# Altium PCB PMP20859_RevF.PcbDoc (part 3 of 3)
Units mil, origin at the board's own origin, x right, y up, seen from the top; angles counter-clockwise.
Board outline 5000 x 4200 mil, 4 copper layers (Top Layer, Signal Layer 1, Signal Layer 2, Bottom Layer), stack 61.2 mil thick; 264 components, 163 nets, 897 pads, 223 vias.
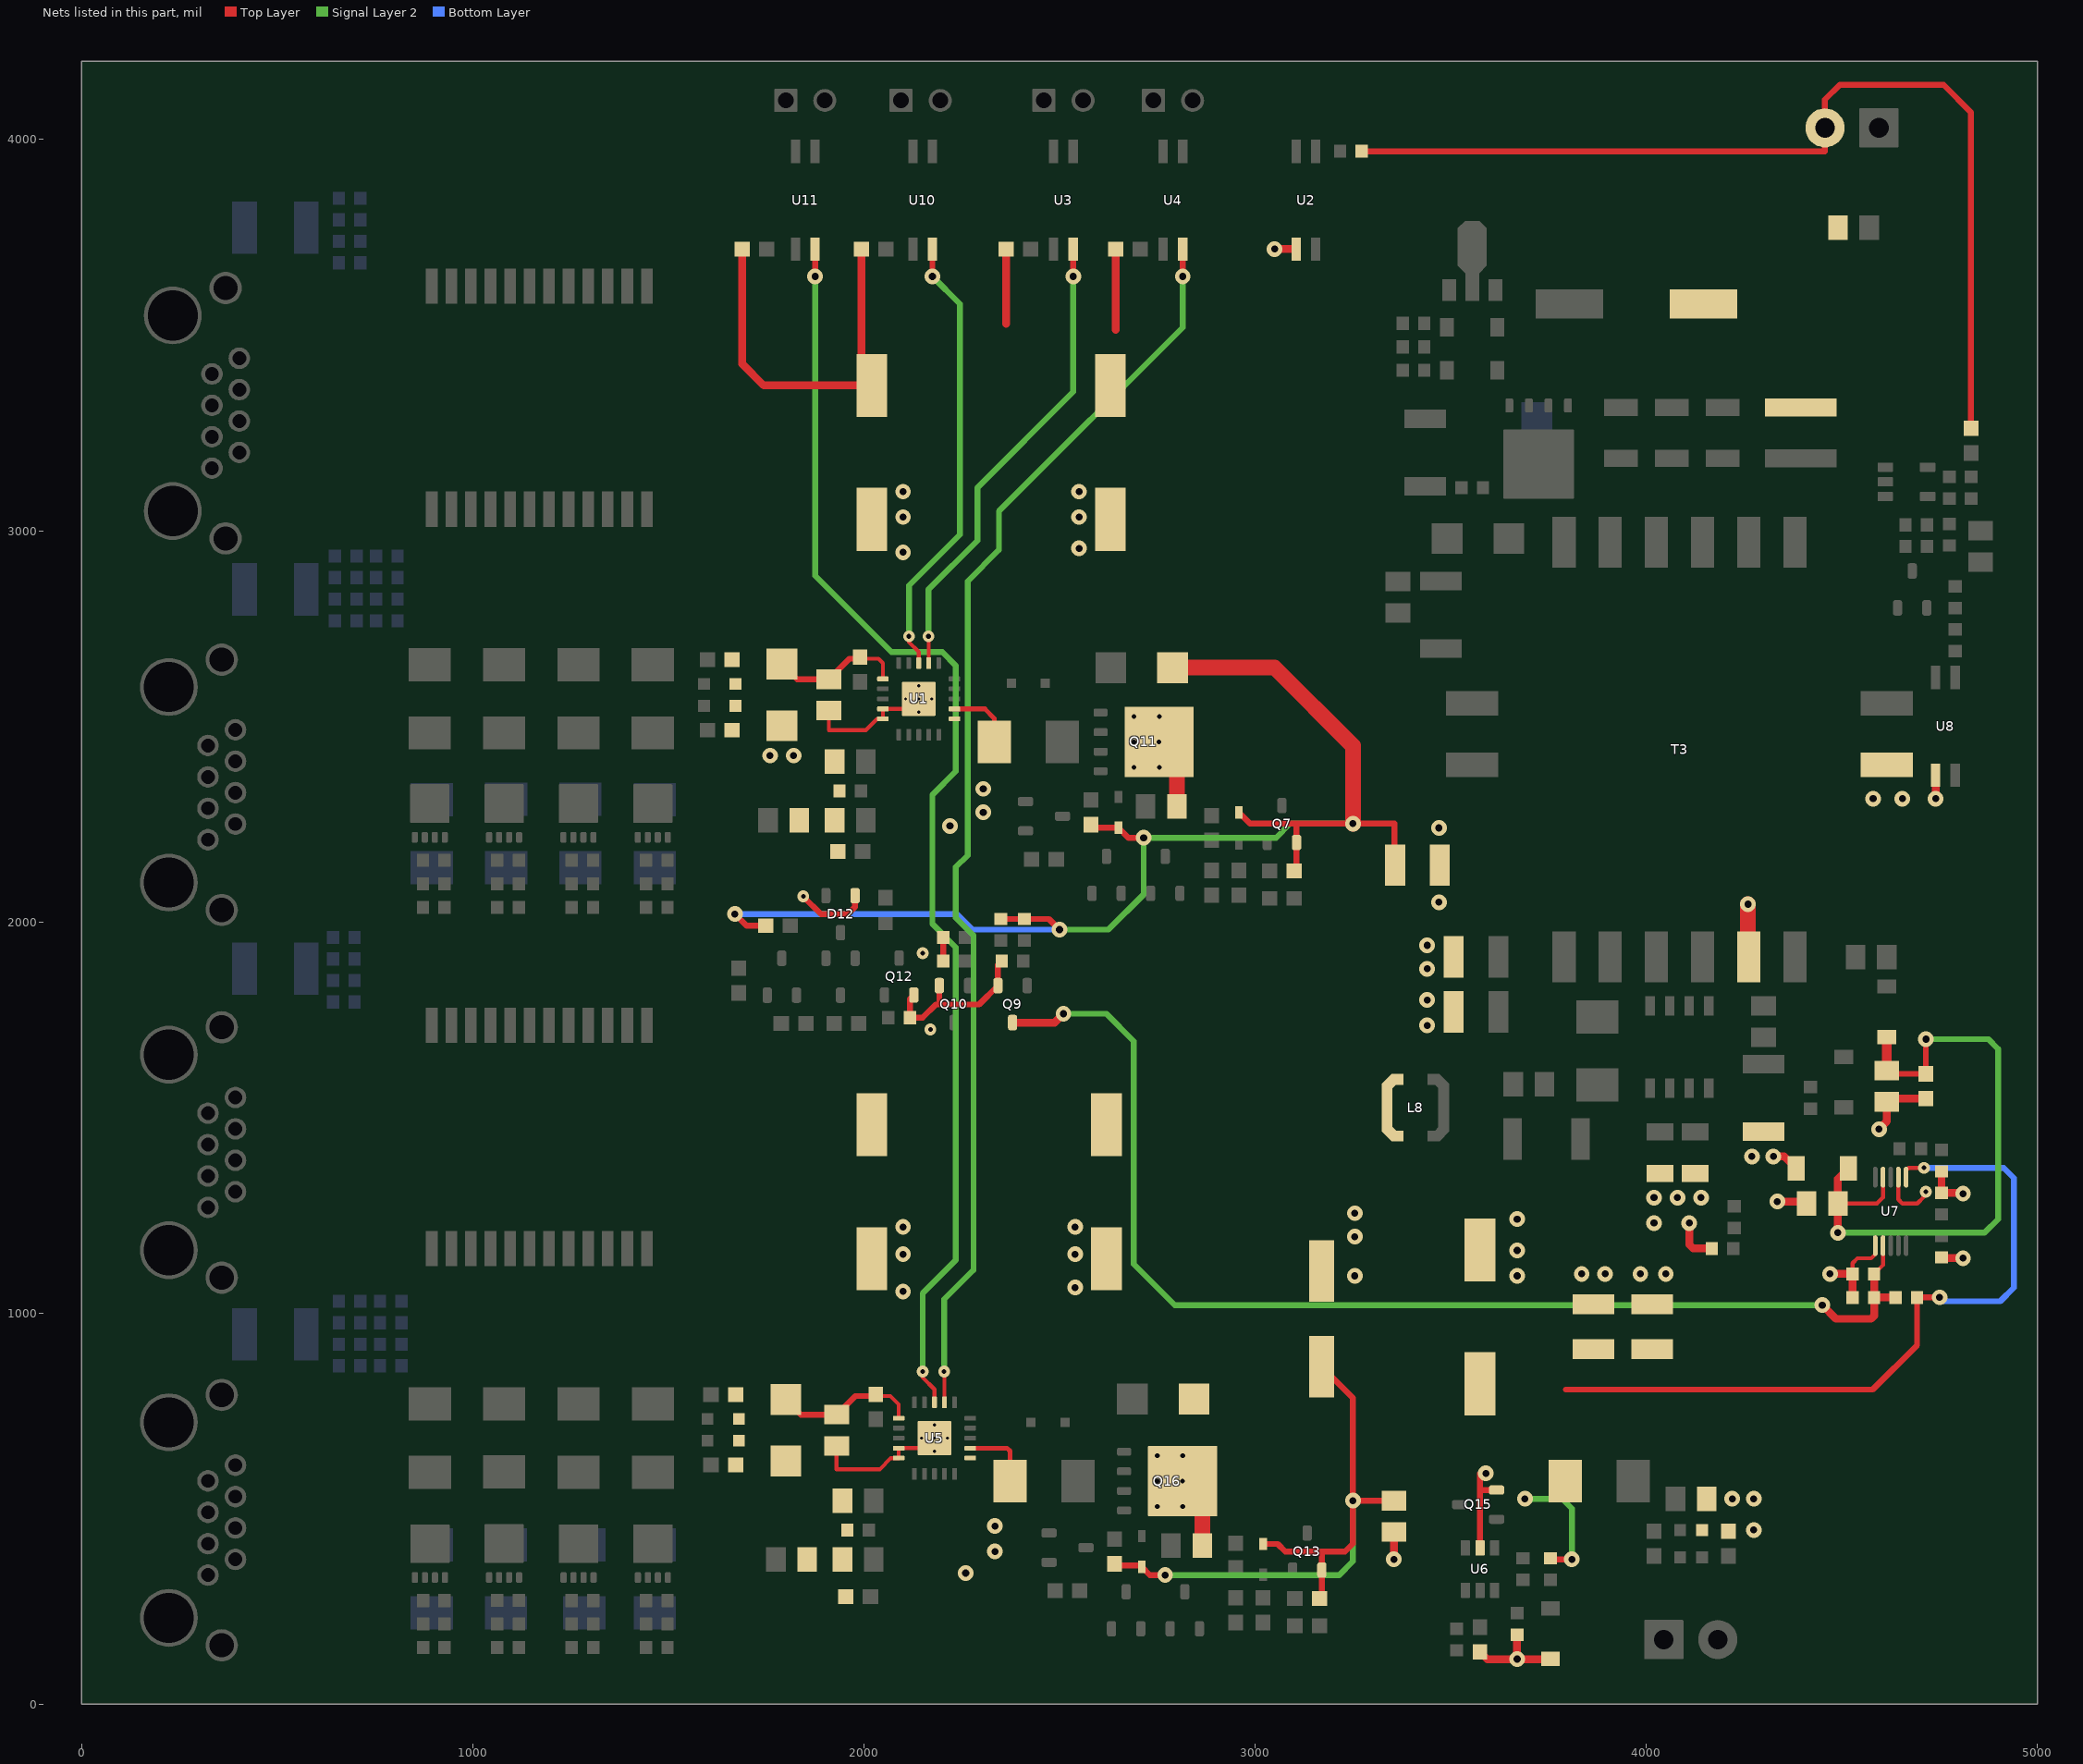
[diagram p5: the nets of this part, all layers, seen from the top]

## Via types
v1: diameter 40, hole 18, Top Layer to Bottom Layer, 185 vias
v2: diameter 30, hole 12, Top Layer to Bottom Layer, 28 vias
v3: diameter 19.68, hole 7.87, Top Layer to Bottom Layer, 10 vias

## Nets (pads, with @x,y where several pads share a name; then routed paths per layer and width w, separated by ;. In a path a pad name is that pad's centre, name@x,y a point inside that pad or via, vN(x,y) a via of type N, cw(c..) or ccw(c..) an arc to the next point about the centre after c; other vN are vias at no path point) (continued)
PWRGND: C30.2 C31.2 C32.2 C33.2 C40.1 C47.2 C48.2 C49.2 C51.2 C53.1 C54.2 C57.1 C58.2 C59.2 C60.1 C61.1 C64.2 C68.1 C69.1 C70.2 C100.1 C101.1 D12.1 D24.2 L6.2 Q9.2 Q10.2 Q11.5 Q11.6 Q11.7 Q11.8 Q11.9@2754.57,2460 Q12.2 Q15.2 Q16.5 Q16.6 Q16.7 Q16.8 Q16.9@2814.57,570 R53.1 R55.1 R57.1 R77.1 R86.1 R87.1 R89.1 R90.1 R93.1 R94.1 T3.5 U2.3 U6.2 U7.2 U7.6 U8.3 | length 2809.7
  Top Layer w10: R86.1@4527.44,1099.69 4527.44,1127.44 4540,1140 4575,1140 4585.63,1150.63 U7.6@4585.63,1178.98 ; U7.2@4644.69,1340.39 4644.69,1290.31 4655,1280 4692.83,1280 v2@4710,1297.17
  Top Layer w15: v2(1845,2065) 1890,2020 1959.37,2020 1977.4,2038.03 D12.1@1977.4,2066.93 ; Q12.2@2127.4,1812.76 2117.56,1802.91 R57.1@2117.56,1755 2150,1755 2183.7,1788.7 2294.37,1788.7 Q9.2@2342.6,1836.93 2342.6,1889.84 R53.1@2352.44,1899.68 ; 2192.6,1797.6 Q10.2@2192.6,1836.93 ; R55.1@2202.13,1900 R55.1@2202.44,1899.68 C30.2@2202.44,1959.68 ; U6.2@3575,399.13 v1@3575,590 ; 3577.6,547.4 Q15.2@3617.24,547.4
  Top Layer w20: v1(3050,3720) U2.3@3105,3720 ; v1(3355,370) C51.2@3355,440 ; R77.1@3575,133.5 3593.5,115 v1(3670,115) ; C40.1@3670,177.44 v1(3670,115) ; D24.2@3754.47,115 v1(3670,115) ; v1(4110,1230) 4110,1175 4120,1165 C64.2@4167.44,1165 ; v1(4325,1400) 4353.07,1400 C54.2@4383.07,1370 ; v1(4335,1285) C53.1@4405,1285 ; v1@4470.31,1099.69 R86.1@4527.44,1099.69 C60.1@4527.44,1039.69 ; v1(4595,1470) 4615,1490 C59.2@4615,1540 4623.5,1548.5 C58.2@4715,1548.5 ; v1(4740,2315) U8.3@4740,2375 ; R89.1@4755,1362.13 R87.1@4755,1307.24 v1@4807.76,1307.24 ; C61.1@4757.13,1140 v1(4810,1140)
  Top Layer w40: v2(2754.57,2460) 2800,2414.57 C68.1@2800,2295 ; v2(2814.57,570) 2865,519.57 C69.1@2865,405 ; T3.5@4260,1912.15 v1(4260,2045)
  other v1: 4275,445 4220,525 4275,525 3590,590 3255,1095 3670,1095 3835,1100 3895,1100 3985,1100 4050,1100 4470,1100 3670,1160 3255,1195 4020,1230 3670,1240 3255,1255 4020,1295 4080,1295 4140,1295 4810,1305 4270,1400 3440,1735 3440,1800 3440,1880 3440,1940 3470,2050 3470,2240 4580,2315 4655,2315
  other v2: 2750,505 2815,505 2750,570 2750,635 2815,635 4715,1310 2170,1725 2150,1920 2690,2395 2755,2395 2690,2460 2690,2525 2755,2525
RTN1: C25.2 C26.2 D16.1 U1.11 U1.12 | length 171.9
  Top Layer w12: U1.12@2231.54,2544.41 2309.09,2544.41 2332.99,2520.51 D16.1@2332.99,2460
  other v1: 2220,2245 2305,2280 2305,2340 2100,2945 2550,2955 2100,3035 2550,3035 2100,3100 2550,3100
RTN2: C35.2 C36.2 D26.1 U5.11 U5.12 | length 181.3
  Top Layer w12: U5.12@2271.85,654.41 2365.59,654.41 2373.31,646.69 D26.1@2373.31,570
  other v1: 2260,335 2335,390 2335,455 2100,1055 2540,1065 2100,1150 2540,1150 2100,1220 2540,1220
SS: C60.2 Q9.3 R82.1 R86.2 U7.7 | length 3122.7
  Top Layer w10: R86.2@4582.56,1099.69 4605.31,1122.44 U7.7@4605.31,1178.98
  Top Layer w20: Q9.3@2380,1742.44 2487.44,1742.44 v1(2510,1765) ; v1(4450,1020) 4485,985 4575,985 4582.56,992.56 C60.2@4582.56,1039.69 ; R86.2@4582.56,1099.69 C60.2@4582.56,1039.69 ; R82.1@4637.44,1039.69 C60.2@4582.56,1039.69
  Signal Layer 2 w15: v1(2510,1765) 2620,1765 2690,1695 2690,1125 2795,1020 v1(4450,1020)
TPH1: U1.18 U10.2 | length 1151.7
  Top Layer w10: v2(2115,2730) 2115,2715 2140,2690 U1.18@2140,2661.54
  Top Layer w15: v1(2175,3650) U10.2@2175,3720
  Signal Layer 2 w15: v2(2115,2730) 2115,2860 2245,2990 2245,3580 v1(2175,3650)
TPH2: U5.18 U11.2 | length 3271.2
  Top Layer w10: v2(2150,850) 2150,835 2180.32,804.68 U5.18@2180.32,771.54
  Top Layer w15: v1(1875,3650) U11.2@1875,3720
  Signal Layer 2 w15: v1(1875,3650) 1875,2885 2070,2690 2200,2690 2235,2655 2235,2385 2175,2325 2175,1995 2235,1935 2235,1135 2150,1050 v2(2150,850)
TPL1: U1.17 U3.2 | length 1211.1
  Top Layer w10: U1.17@2165.59,2661.54 v2@2165.59,2729.41
  Top Layer w15: v1(2535,3650) U3.2@2535,3720
  Signal Layer 2 w15: v2(2165,2730) 2165,2850 2290,2975 2290,3110 2535,3355 v1(2535,3650)
TPL2: U4.2 U5.17 | length 3237.5
  Top Layer w10: U5.17@2205.91,771.54 v2@2205.91,849.09
  Top Layer w15: v1(2815,3650) U4.2@2815,3720
  Signal Layer 2 w15: v2(2205,850) 2205,1035 2280,1110 2280,1965 2235,2010 2235,2140 2265,2170 2265,2871.02 2345,2951.02 2345,3049.69 2815,3519.69 v1(2815,3650)
VCC: C53.2 C54.1 C58.1 C59.1 D30.1 U7.4 | length 1675.3
  Top Layer w10: C53.2@4490,1280 4590,1280 4605.31,1295.32 U7.4@4605.31,1340.39
  Top Layer w15: C59.1@4615,1620 4623.5,1611.5 C58.1@4715,1611.5 v1(4715,1700)
  Top Layer w20: v1(4490,1205) C53.2@4490,1280 4490,1343.07 C54.1@4516.93,1370
  Top Layer w25: C59.1@4615,1620 D30.1@4615,1705.53
  Signal Layer 2 w15: v1(4490,1205) 4600,1205 4865,1205 4900,1240 4900,1675 4875,1700 v1(4715,1700)
VDD: C2.1 C14.1 C25.1 C26.1 C27.2 C31.1 C35.1 C36.1 C37.2 C47.1 C51.1 C70.1 C100.2 C101.2 D9.1 D10.1 D11.1 D13.1 D18.1 D19.1 D20.1 D21.1 D34.1 L1.2 L3.2 L8.1 Q7.2 Q13.2 R33.2 R34.2 R35.2 R36.1 R37.2 R38.1 R49.2 R52.1 R58.1 R59.1 R60.2 R61.2 R62.2 R69.2 R82.2 U1.1 U5.1 U7.1 | length 9662
  Top Layer w10: R35.2@1990,2672.56 2037.44,2672.56 2048.46,2661.54 U1.1@2048.46,2621.18 ; R62.2@2030.32,787.56 2067.44,787.56 2088.78,766.22 U5.1@2088.78,731.18 ; U7.1@4664.37,1364.37 4670.98,1370.98 v2(4710,1370.98)
  Top Layer w15: v1(1670,2020) 1700,1990 R33.2@1748.5,1990 ; D11.1@1790.32,2658.74 1829.05,2620 C27.2@1910.32,2620 1962.87,2672.56 R35.2@1990,2672.56 ; D21.1@1800.32,778.74 1839.05,740 C37.2@1930.32,740 1977.87,787.56 R62.2@2030.32,787.56 ; R52.1@2350,2007.24 2472.76,2007.24 v1(2500,1980) ; R37.2@2580.32,2248.5 2588.19,2240.63 D9.1@2650.32,2240.63 2675.94,2215 v1(2715,2215) ; R61.2@2640.32,358.5 2640.32,354.68 2706.26,354.68 D20.1@2710.32,350.63 2730.94,330 v1(2770,330) ; D10.1@2958.64,2279.37 2987.02,2250.99 v1(3250,2250.99) 3355.99,2250.99 C47.1@3355.99,2146.92 ; D19.1@3020.32,409.37 3057.77,409.37 3077.14,390 3230,390 3250,410 v1(3250,520) ; R34.2@3100.14,2130 3106.04,2135.91 Q7.2@3106.04,2202.76 3106.04,2249.95 ; R60.2@3164.74,270 3170.65,275.91 Q13.2@3170.65,342.76 3170.65,389.35 ; C31.1@3170,862.95 3250,782.95 v1(3250,520) ; C51.1@3355,520 v1(3250,520) ; R69.2@3755,372.56 3757.56,370 v1(3810,370) v1@3807.44,372.56 ; 3795,804.06 4579.06,804.06 4692.56,917.56 R82.2@4692.56,1039.69 4749.69,1039.69 v1(4750,1040)
  Top Layer w20: R38.1@1688.5,3720 1688.5,3426.5 1743.74,3371.26 C25.1@2020,3371.26 1993.5,3397.76 R36.1@1993.5,3720 ; 2363.5,3528.5 R58.1@2363.5,3720 ; 2643.5,3513.5 R59.1@2643.5,3720
  Top Layer w40: D13.1@2788.74,2650 3050,2650 3250,2450 v1(3250,2250.99)
  Signal Layer 2 w15: v1(2500,1980) 2625,1980 2715,2070 v1(2715,2215) 3053.33,2215 3089.32,2250.99 v1(3250,2250.99) ; v1(2770,330) 3215,330 3250,365 v1(3250,520) ; v1(3690,525) 3785,525 3810,500 v1(3810,370)
  Bottom Layer w15: v1(1670,2020) 2237.6,2020 2277.6,1980 v1(2500,1980) ; v2(4710,1370.98) 4914.02,1370.98 4940,1345 4940,1065 4905,1030 4760,1030 v1(4750,1040)
VOUT: C46.1 C50.1 J8.2 L7.2 R56.2 R92.1 | length 2546.7
  Top Layer w15: R56.2@3272.56,3970 4457,3970 J8.2@4457,4030 4457,4102 4495,4140 4760,4140 4830.31,4069.69 R92.1@4830.31,3257.56
VSS_1: C2.2 C27.1 D11.2 L2.2 R42.2 R47.1 R48.1 R50.2 R54.1 U1.4 U1.5 U1.21@2140,2570 | length 328.3
  Top Layer w10: C27.1@1910.32,2540 1910,2539.69 1910,2490 2005,2490 2033.82,2518.82 U1.5@2048.46,2518.82 U1.4@2048.46,2544.41 2114.41,2544.41 v3(2140,2570)
  other v1: 1760,2425 1820,2425
  other v3: 2140,2536.54 2106.54,2570 2173.46,2570 2140,2603.46
VSS_2: C14.2 C37.1 D21.2 L4.2 R67.2 R70.2 R71.1 R72.1 R75.1 U5.4 U5.5 U5.21@2180.32,680 | length 358.6
  Top Layer w10: C37.1@1930.32,660 1930,659.69 1930,600 2040,600 2068.82,628.82 U5.5@2088.78,628.82 U5.4@2088.78,654.41 2154.72,654.41 v3(2180.32,680)
  other v3: 2180.32,646.54 2146.85,680 2213.78,680 2180.32,713.46
pads on no net: D12.2 D15.2 D17.2 D23.2 D25.2 Q1.9@1421.61,2323.37 Q1.9@1433.92,2268.94 Q1.9@1433.92,2304.57 Q1.9@1447.2,2323.37 Q1.9@1460,2290 Q1.9@1472.8,2323.37 Q1.9@1486.08,2268.94 Q1.9@1486.08,2304.57 Q1.9@1498.39,2323.37 Q2.9@1041.61,2323.37 Q2.9@1053.92,2268.94 Q2.9@1053.92,2304.57 Q2.9@1067.2,2323.37 Q2.9@1080,2290 Q2.9@1092.8,2323.37 Q2.9@1106.08,2268.94 Q2.9@1106.08,2304.57 Q2.9@1118.39,2323.37 Q3.9@1231.61,2323.37 Q3.9@1243.92,2268.94 Q3.9@1243.92,2304.57 Q3.9@1257.2,2323.37 Q3.9@1270,2290 Q3.9@1282.8,2323.37 Q3.9@1296.08,2268.94 Q3.9@1296.08,2304.57 Q3.9@1308.39,2323.37 Q4.9@851.61,2323.37 Q4.9@863.92,2268.94 Q4.9@863.92,2304.57 Q4.9@877.2,2323.37 Q4.9@890,2290 Q4.9@902.8,2323.37 Q4.9@916.08,2268.94 Q4.9@916.08,2304.57 Q4.9@928.39,2323.37 Q11.9@2700.04,2402.91 Q11.9@2700.04,2460 Q11.9@2700.04,2517.09 Q11.9@2736.65,2460 Q11.9@2770.12,2402.91 Q11.9@2770.12,2460 Q11.9@2770.12,2517.09 Q16.9@2760.04,512.91 Q16.9@2760.04,570 Q16.9@2760.04,627.09 Q16.9@2796.65,570 Q16.9@2830.12,512.91 Q16.9@2830.12,570 Q16.9@2830.12,627.09 Q17.9@3667.91,3154.88 Q17.9@3667.91,3224.96 Q17.9@3725,3154.88 Q17.9@3725,3188.35 Q17.9@3725,3224.96 Q17.9@3782.09,3154.88 Q17.9@3782.09,3224.96 Q20.9@1421.93,430.94 Q20.9@1434.24,376.51 Q20.9@1434.24,412.14 Q20.9@1447.52,430.94 Q20.9@1460.32,397.58 Q20.9@1473.11,430.94 Q20.9@1486.4,376.51 Q20.9@1486.4,412.14 Q20.9@1498.71,430.94 Q21.9@1041.62,431.26 Q21.9@1053.92,376.83 Q21.9@1053.92,412.46 Q21.9@1067.21,431.26 Q21.9@1080,397.89 Q21.9@1092.8,431.26 Q21.9@1106.09,376.83 Q21.9@1106.09,412.46 Q21.9@1118.39,431.26 Q22.9@1231.93,430.94 Q22.9@1244.24,376.51 Q22.9@1244.24,412.14 Q22.9@1257.52,430.94 Q22.9@1270.32,397.58 Q22.9@1283.11,430.94 Q22.9@1296.4,376.51 Q22.9@1296.4,412.14 Q22.9@1308.71,430.94 Q23.9@851.93,430.94 Q23.9@864.24,376.51 Q23.9@864.24,412.14 Q23.9@877.52,430.94 Q23.9@890.32,397.58 Q23.9@903.11,430.94 Q23.9@916.4,376.51 Q23.9@916.4,412.14 Q23.9@928.71,430.94 U1.10 U1.14 U1.15 U1.16 U1.19 U1.20 U1.21@2116.77,2546.77 U1.21@2116.77,2593.23 U1.21@2163.23,2546.77 U1.21@2163.23,2593.23 U5.10 U5.14 U5.15 U5.16 U5.19 U5.20 U5.21@2157.09,656.77 U5.21@2157.09,703.23 U5.21@2203.54,656.77 U5.21@2203.54,703.23 U6.3 U6.4 U9.1 U9.2

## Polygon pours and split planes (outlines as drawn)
PR12_1 on Bottom Layer "BOTTOM_LAYER_PR12_1_P079" (solid, remove dead copper, pour order 79): 1530,2255 1530,2425 1390,2425 1390,2255
PR36_1 on Bottom Layer "BOTTOM_LAYER_PR36_1_P075" (solid, remove dead copper, pour order 75): 1340,2255 1340,2425 1200,2425 1200,2255
PR45_1 on Bottom Layer "BOTTOM_LAYER_PR45_1_P073" (solid, remove dead copper, pour order 73): 1150,2255 1150,2425 1010,2425 1010,2255
PR78_1 on Bottom Layer "BOTTOM_LAYER_PR78_1_P071" (solid, remove dead copper, pour order 71): 960,2255 960,2425 820,2425 820,2255
NetC1_2 on Bottom Layer "BOTTOM_LAYER_NETC1_2_P069" (solid, remove dead copper, pour order 69): 785,2080 1610,2080 1610,2190 785,2190
PR12_2 on Bottom Layer "BOTTOM_LAYER_PR12_2_P067" (solid, remove dead copper, pour order 67): 1530,360 1530,535 1390,535 1390,360
PR36_2 on Bottom Layer "BOTTOM_LAYER_PR36_2_P065" (solid, remove dead copper, pour order 65): 1340,360 1340,535 1200,535 1200,360
PR45_2 on Bottom Layer "BOTTOM_LAYER_PR45_2_P063" (solid, remove dead copper, pour order 63): 1010,360 1010,535 1150,535 1150,360
PR78_2 on Bottom Layer "BOTTOM_LAYER_PR78_2_P061" (solid, remove dead copper, pour order 61): 960,360 820,360 820,535 960,535
NetC13_2 on Bottom Layer "BOTTOM_LAYER_NETC13_2_P059" (solid, remove dead copper, pour order 59): 785,190 1620,190 1620,295 785,295
RTN2 on Bottom Layer "BOTTOM_LAYER_RTN2_P047" (solid, remove dead copper, pour order 47): 2900,1000 2495,1000 2495,250 2300,250 2300,890 1650,890 1650,1620 2900,1620
RTN1 on Bottom Layer "BOTTOM_LAYER_RTN1_P043" (solid, remove dead copper, pour order 43): 2850,2880 2850,3550 1640,3550 1640,2780 2250,2780 2250,2200 2450,2200 2450,2880
GND on Bottom Layer "BOTTOM_LAYER_GND_P050" (solid, remove dead copper, pour order 50): 3040,4150 1700,4150 1699.79,4150 1700.08,3849.7 3325,3849.7 3325,2675 3475,2525 4950,2525 4950,4150
PWRGND on Bottom Layer "BOTTOM_LAYER_PWRGND_P056" (solid, remove dead copper, pour order 56): 2725,50 2725,950 2950,950 2950,1700 1640.39,1700 1640,1700.39 1640,2100 2665,2100 2665,2800 2950,2800 2950,3750 3225,3750 3225,2595 3385,2435 4950,2435 4950,50 4300,50 4300,420 3950,420 3950,50
BSVG on Bottom Layer "BOTTOM_LAYER_BSVG_P057" (solid, pour order 57): 450,3940 60,3940 60,60 450,60
VSS_1 on Bottom Layer "BOTTOM_LAYER_VSS_1_P032" (solid, pour order 32): 2185,2615 2095,2615 2095,2570 1640,2570 1640,2150 2140,2150 2140,2400 2185,2400
VSS_2 on Bottom Layer "BOTTOM_LAYER_VSS_2_P036" (solid, pour order 36): 2225,725 2135,725 2135,690 1650,690 1650,240 2190,240 2190,500 2225,500
RTN2 on Top Layer "TOP_LAYER_RTN2_P048" (solid, remove dead copper, pour order 48): 2300,890 2300,1000 2900,1000 2900,1300 1910,1300 1910,890
RTN1 on Top Layer "TOP_LAYER_RTN1_P039" (solid, pour order 39): 1900,2780 1900,3200 2850,3200 2850,2880 2250,2880 2250,2780
GND on Top Layer "TOP_LAYER_GND_P052" (solid, remove dead copper, pour order 52): 1700,4150 1700,3850 3324.41,3850 3325,3849.41 3325,2675 3475,2525 4950,2525 4950,4150
PWRGND on Top Layer "TOP_LAYER_PWRGND_P054" (solid, remove dead copper, pour order 54): 2725,950 2950,950 2950,1700 2949.61,1700.39 1640,1700.39 1640,2100 2665,2100 2665,2800 2950,2800 2950,3750 3225,3750 3225,2595 3385,2435 4950,2435 4950,50 4300,50 4300,420 3950,420 3950,50 2725,50
AUX on Top Layer "TOP_LAYER_AUX_P030" (solid, pour order 30): 4105,420 3910,420 3910,665 4105,665
RTN1 on Top Layer "TOP_LAYER_RTN1_P040" (solid, pour order 40): 2215,2550 2385,2550 2385,2380 2365,2380 2365,2200 2190,2200 2190,2325 2250,2325 2250,2475 2215,2510
RTN2 on Top Layer "TOP_LAYER_RTN2_P044" (solid, pour order 44): 2255,660 2425,660 2425,250 2230,250 2230,425 2300,425 2300,575 2255,620
NetC38_2 on Top Layer "TOP_LAYER_NETC38_2_P029" (solid, pour order 29): 2495,495 2595,495 2595,535 2685,535 2685,705 2735,705 2735,840 2610,840 2610,650 2495,650
NetC28_2 on Top Layer "TOP_LAYER_NETC28_2_P028" (solid, pour order 28): 2455,2380 2555,2380 2555,2425 2625,2425 2625,2590 2675,2590 2675,2710 2545,2710 2545,2545 2455,2545
VOUT on Top Layer "TOP_LAYER_VOUT_P027" (solid, pour order 27): 4515,3280 4515,4150 4025,4150 4025,3490 4285,3490 4285,3280
NetC42_2 on Top Layer "TOP_LAYER_NETC42_2_P026" (solid, pour order 26): 3535,2845 3330,2845 3330,3040 3535,3040
NetC56_2 on Top Layer "TOP_LAYER_NETC56_2_P025" (solid, pour order 25): 4305,3040 4215,3040 4215,2780 3825,2780 3825,3260 3565,3260 3565,2680 4305,2680
NetC43_1 on Top Layer "TOP_LAYER_NETC43_1_P024" (solid, pour order 24): 3865,2900 3865,3220 4510,3220 4510,2900 4335,2900 4335,3070 3950,3070 3950,2900
NetC52_2 on Top Layer "TOP_LAYER_NETC52_2_P023" (solid, pour order 23): 3950,1630 3950,1380 3715,1380 3715,1630
NetC63_2 on Top Layer "TOP_LAYER_NETC63_2_P022" (solid, pour order 22): 4360,1730 4360,1595 4240,1595 4240,1730
NetQ19_1 on Top Layer "TOP_LAYER_NETQ19_1_P021" (solid, pour order 21): 3980,1600 3980,1430 4360,1430 4360,1500 4125,1500 4125,1600
NetC41_1 on Top Layer "TOP_LAYER_NETC41_1_P020" (solid, pour order 20): 3435,1380 3435,1650 3555,1650 3570,1665 3585,1680 3585,1980 3950,1980 3950,1840 3685,1840 3685,1380
NetC63_1 on Top Layer "TOP_LAYER_NETC63_1_P019" (solid, pour order 19): 4190,1980 4190,1815 4340,1815 4340,1760 4190,1760 4190,1630 3980,1630 3980,1700 3796.5,1700 3796.5,1815 3980,1815 3980,1980
BSVG on Top Layer "TOP_LAYER_BSVG_P058" (solid, pour order 58): 450,3940 450,60 60,60 60,3940
NetC1_1 on Top Layer "TOP_LAYER_NETC1_1_P000" (solid, pour order 0): 820,2590 1620,2590 1620,2710 820,2710
NetC13_1 on Top Layer "TOP_LAYER_NETC13_1_P001" (solid, pour order 1): 820,715 1630,715 1630,820 820,820
PR78_1 on Top Layer "TOP_LAYER_PR78_1_P002" (solid, pour order 2): 820,2550 820,2305 960,2305 960,2550
PR45_1 on Top Layer "TOP_LAYER_PR45_1_P003" (solid, pour order 3): 1150,2305 1010,2305 1010,2550 1150,2550
PR36_1 on Top Layer "TOP_LAYER_PR36_1_P004" (solid, pour order 4): 1340,2305 1340,2550 1200,2550 1200,2305
PR12_1 on Top Layer "TOP_LAYER_PR12_1_P005" (solid, pour order 5): 1530,2305 1530,2550 1390,2550 1390,2305
NetC1_2 on Top Layer "TOP_LAYER_NETC1_2_P006" (solid, pour order 6): 910,2232.11 910,2197.11 890,2197.11 890,2077.11 785,2077.11 785,2232.11
NetC1_2 on Top Layer "TOP_LAYER_NETC1_2_P007" (solid, pour order 7): 1100,2232.11 1100,2197.11 1080,2197.11 1080,2077.11 975,2077.11 975,2232.11
NetC1_2 on Top Layer "TOP_LAYER_NETC1_2_P008" (solid, pour order 8): 1290,2232.11 1290,2197.11 1270,2197.11 1270,2077.11 1165,2077.11 1165,2232.11
NetC1_2 on Top Layer "TOP_LAYER_NETC1_2_P009" (solid, pour order 9): 1480,2232.11 1480,2197.11 1460,2197.11 1460,2077.11 1355,2077.11 1355,2232.11
PR78_2 on Top Layer "TOP_LAYER_PR78_2_P010" (solid, pour order 10): 960,415 960,650 820,650 820,415
PR45_2 on Top Layer "TOP_LAYER_PR45_2_P011" (solid, pour order 11): 1150,415 1010,415 1010,650 1150,650
PR36_2 on Top Layer "TOP_LAYER_PR36_2_P012" (solid, pour order 12): 1340,415 1340,650 1200,650 1200,415
PR12_2 on Top Layer "TOP_LAYER_PR12_2_P013" (solid, pour order 13): 1390,415 1530,415 1530,650 1390,650
NetC13_2 on Top Layer "TOP_LAYER_NETC13_2_P014" (solid, pour order 14): 910,339.68 910,304.68 890,304.68 890,184.68 785,184.68 785,339.68
NetC13_2 on Top Layer "TOP_LAYER_NETC13_2_P015" (solid, pour order 15): 1100,339.68 975,339.68 975,184.68 1080,184.68 1080,304.68 1100,304.68
NetC13_2 on Top Layer "TOP_LAYER_NETC13_2_P016" (solid, pour order 16): 1290,304.68 1290,339.68 1165,339.68 1165,184.68 1270,184.68 1270,304.68
NetC13_2 on Top Layer "TOP_LAYER_NETC13_2_P017" (solid, pour order 17): 1480,339.68 1480,304.68 1460,304.68 1460,184.68 1355,184.68 1355,339.68
VSS_1 on Top Layer "TOP_LAYER_VSS_1_P031" (solid, pour order 31): 1950,2570 1640,2570 1640,2350 1810,2350 1810,2150 1950,2150 1950,2450
VSS_2 on Top Layer "TOP_LAYER_VSS_2_P035" (solid, pour order 35): 1650,690 1970,690 1970,560 1970,240 1830,240 1830,500 1650,500
VDD on Top Layer "TOP_LAYER_VDD_P018" (solid, pour order 18): 3850,640 3850,420 3665,420 3665,640 2950,640 2950,715 2780,715 2780,950 2950,950 2950,1350 1860,1350 1860,715 1650,715 1650,1620 2950,1620 2950,1900 3200,1900 3200,2350 3172.5,2377.5 3150,2400 2950,2400 2950,2610 2725,2610 2725,2835 2950,2835 2950,3250 1845,3250 1845,2595 1640,2595 1640,3550 3225,3550 3225,2595 3347.5,2472.5 3385,2435 3385,1350 3100,1350 3100,950 3250,950 3850,950 4090,950 4090,705 3850,705
RTN2 on Signal Layer 2 "SIGNAL_LAYER_2_RTN2_P046" (solid, remove dead copper, pour order 46): 1650,1620 2900,1620 2900,1000 2495,1000 2495,250 2300,250 2300,890 1650,890
RTN1 on Signal Layer 2 "SIGNAL_LAYER_2_RTN1_P042" (solid, remove dead copper, pour order 42): 1640,3550 2850,3550 2850,2850 2450,2850 2450,2200 2250,2200 2250,2780 1640,2780
GND on Signal Layer 2 "SIGNAL_LAYER_2_GND_P051" (solid, remove dead copper, pour order 51): 4950,2525 3475,2525 3325,2675 3325,3850 1700,3849.5 1700,4149.63 4950,4150
PWRGND on Signal Layer 2 "SIGNAL_LAYER_2_PWRGND_P055" (solid, remove dead copper, pour order 55): 2725,50 2725,950 2950,950 2950,1700 1640,1700 1640,2100 2665,2100 2665,2800 2950,2800 2950,3750 3225,3750 3225,2595 3385,2435 4950,2435 4950,50 4300,50 4300,420 3950,420 3950,50 2725,50
VSS_2 on Signal Layer 2 "SIGNAL_LAYER_2_VSS_2_P038" (solid, pour order 38): 2190,240 1650,240 1650,690 2135,690 2135,725 2225,725 2225,500 2190,500
VSS_1 on Signal Layer 2 "SIGNAL_LAYER_2_VSS_1_P033" (solid, pour order 33): 2140,2150 1640,2150 1640,2570 2095,2570 2095,2615 2185,2615 2185,2400 2140,2400
VSS_2 on Signal Layer 1 "SIGNAL_LAYER_1_VSS_2_P037" (solid, pour order 37): 2190,240 2190,500 2225,500 2225,725 2135,725 2135,690 1895,690 1650,690 1650,240
RTN1 on Signal Layer 1 "SIGNAL_LAYER_1_RTN1_P041" (solid, pour order 41): 2150,2780 1640,2780 1640,3550 2850,3550 2850,2880 2450,2880 2450,2200 2190,2200 2190,2325 2250,2325 2250,2780
RTN2 on Signal Layer 1 "SIGNAL_LAYER_1_RTN2_P045" (solid, pour order 45): 2200,890 1650,890 1650,1620 2900,1620 2900,1000 2495,1000 2495,250 2230,250 2230,425 2300,425 2300,890
GND on Signal Layer 1 "SIGNAL_LAYER_1_GND_P049" (solid, pour order 49): 3475,2525 3325,2675 3325,3850 1700,3850 1700,4150 4950,4150 4950,2525
PWRGND on Signal Layer 1 "SIGNAL_LAYER_1_PWRGND_P053" (solid, pour order 53): 4950,2435 4950,975 4950,50 4300,50 4300,420 4125,420 3950,420 3950,50 2725,50 2725,950 2950,950 2950,1700 1640,1700 1640,2100 2665,2100 2665,2800 2950,2800 2950,3750 3225,3750 3225,2595 3305,2515 3385,2435
VSS_1 on Signal Layer 1 "SIGNAL_LAYER_1_VSS_1_P034" (solid, pour order 34): 2140,2150 2140,2400 2185,2400 2185,2615 2095,2615 2095,2570 1640,2570 1640,2150

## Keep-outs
Keep-Out Layer:
  lines w10: -5,0 ccw(c0,0) 0,-5 ; -5,0 ccw(c0,0) 0,-5 ; -5,0 -5,4200 ; -5,4200 cw(c0,4200) 0,4205 ; -5,4200 cw(c0,4200) 0,4205 ; 0,-5 5000,-5 ; 0,4205 5000,4205 ; 5000,-5 ccw(c5000,0) 5005,0 ; 5000,-5 ccw(c5000,0) 5005,0 ; 5000,4205 cw(c5000,4200) 5005,4200 ; 5000,4205 cw(c5000,4200) 5005,4200 ; 5005,0 5005,4200
  text ".Layer_Name" at 577,-858.49 h60

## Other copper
Top Layer:
  text ".Layer_Name" at 577,-858.49 h60
Bottom Layer:
  text ".Layer_Name" at 577,-858.49 h60

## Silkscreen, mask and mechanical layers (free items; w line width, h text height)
Top Overlay:
  region: 1500,4135 735,4135 735,4035 1500,4035
  lines w8: 1020,235 1030,245 1030,295 ; 1090,105 1090,45 1970,45 ; 1210,225 1220,235 1220,295 ; 1285,45 1285,105 ; 1700,45 1700,215 ; 1840,45 1840,215 ; 2195,215 2195,165 2445,165 ; 2400,165 2400,440 2435,475 ; 2888.64,2320 2913.64,2345 3005,2345 3015,2345 3265,2345 ; 3370,3060 3535,3060 3555,3080 ; 3680,3525 3705,3550 3705,3630 ; 4775,3175 4775,3190 4785,3200 4785,3225 4785,3510
  text "'.PRJ_Number'.PCB_Rev-" at 140,4050 h108.27
  text ".Layer_Name" at 577,-858.49 h60
Bottom Overlay:
  text ".Layer_Name" at 577,-858.49 h60
Top Paste:
  text ".Layer_Name" at 577,-858.49 h60
Bottom Paste:
  text ".Layer_Name" at 577,-858.49 h60
Top Solder:
  text ".Layer_Name" at 577,-858.49 h60
  text ".Layer_Name" at 577,-858.49 h60
Bottom Solder:
  text ".Layer_Name" at 577,-858.49 h60
Drill Guide:
  text ".Layer_Name" at 577,-858.49 h60
M1 Board Outline:
  the board outline again, w10
  text ".Layer_Name" at 577,-858.49 h60
M2 Board Dimensions:
  rectangle: 0,-275 125,-150
  rectangle: 125,-400 500,-275
  lines w7: 0,-275 1000,-275 ; 125,-400 125,-150 ; 250,-400 250,-150 ; 500,-400 500,-150 ; 750,-400 750,-150 ; 0,-400 1000,-400 1000,-150 0,-150 0,-400
  text ".Layer_Name" at 577,-858.49 h60
M3 3D STEP Top:
  text ".Layer_Name" at 577,-858.49 h60
M4 3D STEP Bottom:
  text ".Layer_Name" at 577,-858.49 h60
M5 Assembly Top:
  lines w10: -292,-930.17 6308,-930.17 ; -292,-726.83 6310,-726.83 ; -292,-523.5 -292,-1133.5 3713,-1133.5 6310,-1133.5 6310,-523.5 -291.5,-523.5 -291.5,-1133.5 1284,-1133.5 ; 2173,-1133.5 2173,-523.5 ; 3440,-726.83 3440,-523.5 ; 4280,-726.83 4280,-523.5 ; 4902,-1140 4902,-937.17
  text "COMPONENTS MARKED 'DNP' SHOULD NOT BE POPULATED." at 1153.5,-318.5 h60
  text "ASSEMBLY VARIANT:" at 1153,-434 h60
  text ".VariantName" at 2189,-434 h60
  text "PCB VIEWED FROM TOP SIDE" at -228.5,-655.67 h60
  text "BOARD #:" at 2248,-655.67 h60
  text ".PRJ_Number" at 2793.5,-655.67 h60
  text "REV:" at 3638,-655.67 h60
  text ".PCB_Rev" at 3929.5,-655.67 h60
  text "SVN REV:" at 4476,-655.67 h60
  text ".VersionControl_RevNumber" at 4982,-655.67 h60
  text "TID #:" at 2248,-859 h60
  text ".TID" at 2793.5,-859 h60
  text "PLOT NAME =" at -228.5,-1064.34 h60
  text ".plot_File_Name" at 577,-1064.34 h60
  text "GENERATED    :" at 2250,-1064.34 h60
  text ".Print_Date" at 3119.5,-1064.34 h60
  text ".Print_Time" at 3848.5,-1064.34 h60
  text "TEXAS INSTRUMENTS" at 5113,-1064.34 h60
M6 Assembly Bottom:
  lines w10: -292.5,-727.33 6309.5,-727.33 ; -290.5,-930.67 6309.5,-930.67 ; 1115.5,-1140.5 1115.5,-937.67 ; 1737.5,-727.33 1737.5,-524 ; 2577.5,-727.33 2577.5,-524 ; 3844.5,-1134 3844.5,-524 ; 4733.5,-1134 6309,-1134 6309,-524 -292.5,-524 -292.5,-1134 2304.5,-1134 6309.5,-1134 6309.5,-524
  text "COMPONENTS MARKED 'DNP' SHOULD NOT BE POPULATED." at 6102,-318 h60
  text ".VariantName" at 5058,-434 h60
  text "ASSEMBLY VARIANT:" at 6097,-434 h60
  text ".VersionControl_RevNumber" at 1035.5,-656.17 h60
  text "SVN REV:" at 1541.5,-656.17 h60
  text ".PCB_Rev" at 2088,-656.17 h60
  text "REV:" at 2379.5,-656.17 h60
  text ".PRJ_Number" at 3224,-656.17 h60
  text "BOARD #:" at 3769.5,-656.17 h60
  text "PCB VIEWED FROM BOTTOM SIDE" at 6246,-656.17 h60
  text ".TID" at 3224,-859.5 h60
  text "TID #:" at 3769.5,-859.5 h60
  text "TEXAS INSTRUMENTS" at 904.5,-1064.84 h60
  text ".Print_Time" at 2169,-1064.84 h60
  text ".Print_Date" at 2898,-1064.84 h60
  text "GENERATED    :" at 3767.5,-1064.84 h60
  text ".plot_File_Name" at 5440.5,-1064.84 h60
  text "PLOT NAME =" at 6246,-1064.84 h60
M9 Title Sheet:
  drawing of 57 lines, arcs and shapes, not listed
  text "1" at 739.84,8036.5 h70
  text "2" at 3235.5,8036.5 h70
  text "3" at 5724.84,8036.5 h70
  text "4" at 8231.51,8036.5 h70
  text "5" at 10730.5,8036.5 h70
  text "6" at 13235.5,8036.5 h70
  text "A" at -416.5,6893.5 h70
  text "A" at 14383.5,6893.5 h70
  text "B" at -416.5,4513.5 h70
  text "B" at 14383.5,4513.5 h70
  text "C" at -416.5,2138.5 h70
  text "C" at 14383.5,2138.5 h70
  text "PROJECT TITLE:" at 11343.5,277.5 h45
  text ".PRJ_Title" at 11393.5,144.17 h70
  text "DESIGNED FOR:" at 11343.5,-23.5 h45
  text ".PRJ_Customer" at 11393.5,-163.5 h70
  text "D" at -416.5,-231.5 h70
  text "D" at 14383.5,-231.5 h70
  text "FILE NAME:" at 11343.5,-323.5 h45
  text ".PCB_File_Name_No_Path" at 11393.5,-443.5 h70
  text "Texas Instruments (TI) and/or its licensors do not warrant the accuracy or completeness of this specification" at 6374,-605.34 h45
  text "ENGINEER:" at 11343.5,-613.5 h45
  text "LAYOUT BY:" at 12848.5,-613.5 h45
  text "or any information contained therein. TI and/or its licensors do not warrant that this design will meet" at 6329.01,-718 h45
  text ".PRJ_Engineer" at 11393.5,-768.49 h70
  text ".PCB_Layout" at 12899,-768.49 h70
  text "the specifications, will be suitable for your application or fit for any particular purpose, or will operate in" at 6329.01,-830.67 h45
  text ".Layer_Name" at 577,-858.49 h60
  text "ALTIUM DESIGNER VERSION:" at 12848.5,-923.5 h45
  text "an implementation. TI and/or its licensors do not warrant that the design is production worthy. You should" at 6329.01,-943.33 h45
  text "completely validate and test your design implementation to confirm the system functionality for your application." at 6374,-1056 h45
  text ".print_Scale" at 11393.5,-1056.83 h70
  text ".Application_BuildNumber" at 12899,-1056.83 h70
  text "1" at 739.84,-1263.5 h70
  text "2" at 3235.5,-1263.5 h70
  text "3" at 5724.84,-1263.5 h70
  text "4" at 8231.51,-1263.5 h70
  text "5" at 10730.5,-1263.5 h70
  text "6" at 13235.5,-1263.5 h70
M10 Fab Notes:
  drawing of 173 lines, arcs and shapes, not listed
  text "DESIGN INFORMATION" at 12378.02,6201 h60
  text "MIN. TRACK WIDTH:" at 11733.46,6021 h60
  text "8" at 12829.7,6021 h60
  text "MIL" at 12984.46,6021 h60
  text "MIN. CLEARANCE:" at 11733.46,5889 h60
  text "0.2" at 12769.7,5889 h60
  text "mm" at 12984.46,5889 h60
  text "MIN. VIA PAD SIZE:" at 11733.46,5757 h60
  text "24" at 12799.71,5757 h60
  text "MIL" at 12984.46,5757 h60
  text "0.05mm (2MIL)" at 12428.46,5615.29 h60
  text "MINIMUM ANNULAR RING" at 11404.23,5611 h60
  text "EXTERNAL" at 13136.46,5611 h60
  text "PER" at 11604.23,5493 h60
  text "IPC-D-275 CLASS 2 LEVEL C" at 11824.23,5493 h60
  text "MIL, HOLES" at 13312.46,5380.71 h60
  text "+/-" at 12920,5380 h60
  text "+/-" at 13774,5380 h60
  text "REGISTRATION TOLERANCES:" at 11404.23,5375 h60
  text "METAL" at 12604,5375 h60
  text "5" at 13180.2,5375 h60
  text "3" at 14013.2,5375 h60
  text "MIL" at 14129.46,5375 h60
  text "+/-" at 13774,5262 h60
  text "HOLE SIZE TOLERANCE (UNLESS OTHERWISE SPECIFIED):" at 11404.23,5257 h60
  text "3" at 14013.2,5257 h60
  text "MIL" at 14129.46,5257 h60
  text "MATERIAL:" at 11329.46,5047.54 h60
  text "FR-4 High Tg" at 12315.9,4907.21 h60
  text "FR-408" at 11750.46,4898.64 h60
  text "OTHER" at 13238.46,4898.64 h60
  text "X" at 12161,4895 h60
  text "62 MIL (1.6mm) +/-10%" at 12070.56,4735.92 h60
  text "THICKNESS:" at 11404.23,4731.64 h60
  text "X" at 11942.4,4731.64 h60
  text "OTHER" at 13355.46,4731.64 h60
  text "TOLERANCE:" at 11404.23,4573.64 h60
  text "X" at 12243.53,4573.64 h60
  text "ANSI IPC-6012 TYPE 3 CLASS 2" at 12430.48,4573.64 h60
  text "OTHER +/-" at 12430.46,4417.64 h60
  text "BOW & TWIST:" at 11404.23,4260.64 h60
  text "X" at 12243.53,4260.64 h60
  text "ANSI IPC-6012 TYPE 3 CLASS 2" at 12430.48,4260.64 h60
  text "OTHER +/-" at 12430.46,4102.13 h60
  text "DRILLING:" at 11329.46,3963.64 h60
  text "REFERENCE:" at 11404.23,3846.64 h60
  text "X" at 12052.46,3846.64 h60
  text "AS SHOWN" at 12239.46,3846.64 h60
  text "X" at 12953.46,3846.64 h60
  text "NC_DRILL FILES" at 13090.46,3846.64 h60
  text "PTH COPPER THICKNESS:" at 11404.23,3688.64 h60
  text "X" at 12534.46,3688.64 h60
  text "20-30 um" at 12671.46,3688.64 h60
  text "OTHER" at 13388.46,3688.64 h60
  text "BOARD FINISH:" at 11329.46,3529.64 h60
  text "SILKSCREEN:" at 11484.68,3411.64 h60
  text "X" at 12433.46,3411.64 h60
  text "TOP" at 12559.46,3411.64 h60
  text "X" at 12943.46,3411.64 h60
  text "BOTTOM" at 13070.46,3411.64 h60
  text "SILKSCREEN COLOR:" at 11484.68,3244.64 h60
  text "X" at 12432.42,3244.64 h60
  text "WHITE" at 12559.46,3244.64 h60
  text "OTHER" at 13070.46,3244.64 h60
  text "X" at 12563.42,3085.44 h60
  text "GREEN" at 12690.46,3085.44 h60
  text "OTHER" at 13308.46,3085.44 h60
  text "SOLDER RESIST COLOR:" at 11484.68,3074.64 h60
  text "X" at 12563.42,2915.44 h60
  text "MATTE" at 12690.46,2915.44 h60
  text "SEMI-GLOSS" at 13308,2914.8 h60
  text "IMMERSION GOLD (ENIG)" at 12390.46,2726.92 h60
  text "ENEPIG" at 13728,2723.64 h60
  text "SURFACE FINISH:" at 11329.46,2722.64 h60
  text "X" at 12203.51,2722.64 h60
  text "IMM. TIN/SILVER OR EQUIV" at 11659,2565.64 h60
  text "OTHER" at 13090.46,2565.64 h60
  text "ARRAY/PANEL:" at 11329.46,2386.64 h60
  text "CUT AND TRIM PER M1 BOARD OUTLINE" at 12390.46,2382.35 h60
  text "X" at 12200,2380 h60
  text "N.C. ROUTE" at 12390.46,2230.64 h60
  text "V. SCORE" at 13256.46,2230.64 h60
  text "CERTIFICATION:" at 11329.46,2093.64 h60
  text "MATERIALS AND WORKMANSHIP FOR ALL PCBS" at 12054.46,2093.64 h60
  text "TO MEET OR EXCEED THE REQUIREMENTS OF:" at 12054.46,1995.64 h60
  text "X" at 11680.96,1859.13 h60
  text "ANSI IPC-A-600F CLASS ->" at 11819.96,1859.13 h60
  text "X" at 13459.02,1859.13 h60
  text "2" at 13577.96,1859.14 h60
  text "1" at 13262.96,1857.64 h60
  text "3" at 13931.96,1857.64 h60
  text "X" at 12495.02,1699.64 h60
  text "RoHS" at 12631.96,1699.64 h60
  text "OTHER" at 13276.36,1699.64 h60
  text "PER ORDER" at 13673.42,1699.64 h60
  text "ALL BOARDS MUST MEET OR EXCEED UL94-V0 REQUIREMENTS." at 11357,1534 h60
  text "PCB MUST BEAR THE UL94V-0 UL REGISTERED MATERIAL ID NUMBER" at 11357,1414 h60
  text "ADDITIONAL REQUIREMENTS:" at 11329.46,1240.64 h60
  text "MICROSECTION:" at 11404.23,1125.64 h60
  text "YES" at 12309.96,1125.64 h60
  text "REQUIRED" at 13171.46,969.49 h60
  text "BARE BOARD ELEC. TEST:" at 11404.23,966.64 h60
  text "NONE" at 12709.96,966.64 h60
  text "X" at 13044.46,966.64 h60
  text "PER ORDER" at 13763.46,966.64 h60
  text ".Layer_Name" at 577,-858.49 h60
M11 Gerber Information:
  lines w10: -292,-930.17 6308,-930.17 ; -292,-726.83 6310,-726.83 ; -292,-523.5 -292,-1133.5 3713,-1133.5 6310,-1133.5 6310,-523.5 -291.5,-523.5 -291.5,-1133.5 1284,-1133.5 ; 2173,-1133.5 2173,-523.5 ; 3440,-726.83 3440,-523.5 ; 4280,-726.83 4280,-523.5 ; 4902,-1140 4902,-937.17
  text "ALL ARTWORK VIEWED FROM TOP SIDE" at -228.5,-655.67 h60
  text "BOARD #:" at 2248,-655.67 h60
  text ".PRJ_Number" at 2793.5,-655.67 h60
  text "REV:" at 3638,-655.67 h60
  text ".PCB_Rev" at 3929.5,-655.67 h60
  text "SVN REV:" at 4476,-655.67 h60
  text ".VersionControl_RevNumber" at 4982,-655.67 h60
  text "LAYER NAME =" at -228.5,-858.49 h60
  text "TID #:" at 2248,-859 h60
  text ".TID" at 2793.5,-859 h60
  text "PLOT NAME =" at -228.5,-1064.34 h60
  text ".plot_File_Name" at 577,-1064.34 h60
  text "GENERATED    :" at 2250,-1064.34 h60
  text ".Print_Date" at 3119.5,-1064.34 h60
  text ".Print_Time" at 3848.5,-1064.34 h60
  text "TEXAS INSTRUMENTS" at 5113,-1064.34 h60
M12 Stackup:
  drawing of 295 lines, arcs and shapes, not listed
  text "Layer" at 9725.09,7805 h60
  text "Name" at 10135,7805 h60
  text "Material" at 11074.74,7805 h60
  text "Thickness" at 11934.51,7805 h60
  text "Constant" at 12584.34,7805 h60
  text "Board Layer Stack" at 13154.2,7805 h60
  text "1" at 9725.09,7685 h60
  text "Top Overlay" at 10135,7685 h60
  text "2" at 9725.09,7565 h60
  text "Top Solder" at 10135,7565 h60
  text "Solder Resist" at 11074.74,7565 h60
  text "0.40mil" at 11934.51,7565 h60
  text "3.5" at 12584.34,7565 h60
  text "3" at 9725.09,7445 h60
  text "Top Layer" at 10135,7445 h60
  text "Copper" at 11074.74,7445 h60
  text "2.80mil" at 11934.51,7445 h60
  text "4" at 9725.09,7325 h60
  text "Dielectric1" at 10135,7325 h60
  text "FR-4" at 11074.74,7325 h60
  text "15.00mil" at 11934.51,7325 h60
  text "4.8" at 12584.34,7325 h60
  text "5" at 9725.09,7205 h60
  text "Signal Layer 1" at 10135,7205 h60
  text "Copper" at 11074.74,7205 h60
  text "2.80mil" at 11934.51,7205 h60
  text "6" at 9725.09,7085 h60
  text "Dielectric 2" at 10135,7085 h60
  text "20.00mil" at 11934.51,7085 h60
  text "4.2" at 12584.34,7085 h60
  text "7" at 9725.09,6965 h60
  text "Signal Layer 2" at 10135,6965 h60
  text "Copper" at 11074.74,6965 h60
  text "2.80mil" at 11934.51,6965 h60
  text "8" at 9725.09,6845 h60
  text "Dielectric 3" at 10135,6845 h60
  text "15.00mil" at 11934.51,6845 h60
  text "4.2" at 12584.34,6845 h60
  text "9" at 9725.09,6725 h60
  text "Bottom Layer" at 10135,6725 h60
  text "Copper" at 11074.74,6725 h60
  text "2.80mil" at 11934.51,6725 h60
  text "10" at 9725.09,6605 h60
  text "Bottom Solder" at 10135,6605 h60
  text "Solder Resist" at 11074.74,6605 h60
  text "0.40mil" at 11934.51,6605 h60
  text "3.5" at 12584.34,6605 h60
  text "11" at 9725.09,6485 h60
  text "Bottom Overlay" at 10135,6485 h60
  text ".Layer_Name" at 577,-858.49 h60
M13 Component Bodies Top:
  text ".Layer_Name" at 577,-858.49 h60
M14 Component Bodies Bottom:
  text ".Layer_Name" at 577,-858.49 h60
M15 Courtyards Top:
  text ".Layer_Name" at 577,-858.49 h60
M16 Courtyards Bottom:
  text ".Layer_Name" at 577,-858.49 h60
Drill Drawing:
  circle w10: c5313.72,708.32 r27.63
  lines w10: 5286.09,183.42 5313.72,197.23 5341.34,183.42 5327.53,211.04 5341.34,238.67 5313.72,224.86 5286.09,238.67 5299.9,211.04 5286.09,183.42 ; 5286.09,321.55 5299.9,321.55 5313.72,307.74 5327.53,321.55 5341.34,321.55 5327.53,335.36 5341.34,349.18 5327.53,349.18 5313.72,362.99 5299.9,349.18 5286.09,349.18 5299.9,335.36 5286.09,321.55 ; 5286.09,432.06 5341.34,432.06 5341.34,487.31 5286.09,487.31 5286.09,432.06 ; 5286.09,611.63 5341.34,611.63 5313.72,556.38 5286.09,611.63 ; 5286.09,832.64 5313.72,805.02 5341.34,832.64 5313.72,860.27 5286.09,832.64 ; 5286.09,929.34 5341.34,929.34 5341.34,984.59 5286.09,984.59 5286.09,929.34 ; 5286.09,1053.66 5286.09,1067.47 5299.9,1081.28 5286.09,1095.1 5286.09,1108.91 5299.9,1108.91 5313.72,1095.1 5327.53,1108.91 5341.34,1108.91 5341.34,1095.1 5327.53,1081.28 5341.34,1067.47 5341.34,1053.66 5327.53,1053.66 5313.72,1067.47 5299.9,1053.66 5286.09,1053.66 ; 5297.14,940.39 5330.29,940.39 5330.29,973.54 5297.14,973.54 5297.14,940.39
  lines w12: 5236,146.12 8467.49,146.12 ; 5236,1140.68 8467.49,1140.68 ; 5573.86,21.8 5573.86,1265 ; 5905.86,21.8 5905.86,1265 ; 6542.43,21.8 6542.43,1265 ; 6801.57,21.8 6801.57,1265 ; 7176.72,21.8 7176.72,1265 ; 7901.05,21.8 7901.05,1265 ; 5236,21.8 8467.49,21.8 8467.49,1265 5236,1265 5236,21.8
  text "Symbol" at 5310.59,1177.98 h72
  text "Quantity" at 5611.16,1177.98 h72
  text "Finished Hole Size" at 5943.16,1177.98 h72
  text "Plated" at 6579.72,1177.98 h72
  text "Hole Type" at 6838.86,1177.98 h72
  text "Drill Layer Pair" at 7214.02,1177.98 h72
  text "Hole Tolerance" at 7938.35,1177.98 h72
  text "10" at 5611.16,1053.66 h60
  text "7.87mil (0.200mm)" at 5943.16,1053.66 h60
  text "PTH" at 6579.72,1053.66 h60
  text "Round" at 6838.86,1053.66 h60
  text "Top Layer - Bottom Layer" at 7214.02,1053.66 h60
  text "28" at 5611.16,929.34 h60
  text "12.00mil (0.305mm)" at 5943.16,929.34 h60
  text "PTH" at 6579.72,929.34 h60
  text "Round" at 6838.86,929.34 h60
  text "Top Layer - Bottom Layer" at 7214.02,929.34 h60
  text "185" at 5611.16,805.02 h60
  text "18.00mil (0.457mm)" at 5943.16,805.02 h60
  text "PTH" at 6579.72,805.02 h60
  text "Round" at 6838.86,805.02 h60
  text "Top Layer - Bottom Layer" at 7214.02,805.02 h60
  text "32" at 5611.16,680.7 h60
  text "35.04mil (0.890mm)" at 5943.16,680.7 h60
  text "PTH" at 6579.72,680.7 h60
  text "Round" at 6838.86,680.7 h60
  text "Top Layer - Bottom Layer" at 7214.02,680.7 h60
  text "8" at 5611.16,556.38 h60
  text "40.00mil (1.016mm)" at 5943.16,556.38 h60
  text "PTH" at 6579.72,556.38 h60
  text "Round" at 6838.86,556.38 h60
  text "Top Layer - Bottom Layer" at 7214.02,556.38 h60
  text "4" at 5611.16,432.06 h60
  text "50.00mil (1.270mm)" at 5943.16,432.06 h60
  text "PTH" at 6579.72,432.06 h60
  text "Round" at 6838.86,432.06 h60
  text "Top Layer - Bottom Layer" at 7214.02,432.06 h60
  text "8" at 5611.16,307.74 h60
  text "61.81mil (1.570mm)" at 5943.16,307.74 h60
  text "PTH" at 6579.72,307.74 h60
  text "Round" at 6838.86,307.74 h60
  text "Top Layer - Bottom Layer" at 7214.02,307.74 h60
  text "8" at 5611.16,183.42 h60
  text "128.00mil (3.251mm)" at 5943.16,183.42 h60
  text "PTH" at 6579.72,183.42 h60
  text "Round" at 6838.86,183.42 h60
  text "Top Layer - Bottom Layer" at 7214.02,183.42 h60
  text "283 Total" at 5611.16,59.1 h60
  text ".Layer_Name" at 577,-858.49 h60
M17 Embedded Cavity:
  text ".Layer_Name" at 577,-858.49 h60
M18 Embedded Assembly:
  text ".Layer_Name" at 577,-858.49 h60
M19 Embedded Keepout:
  text ".Layer_Name" at 577,-858.49 h60

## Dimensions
0,-400 to 1000,-400 on M2 Board Dimensions
0,0 to 0,4200 on M2 Board Dimensions
0,0 to 5000,0 on M2 Board Dimensions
